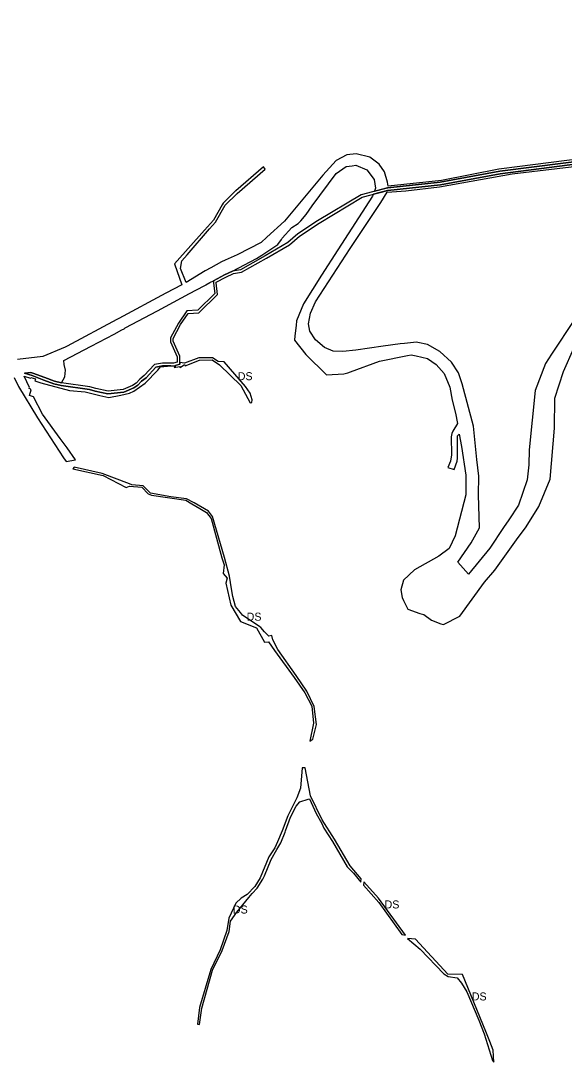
# Model space of a CAD drawing. Extents: x -477304 to -465641, y -1159113 to -1149285.
# Drawn here: x -467453 to -466842, y -1153824 to -1152653 of the extents above; entities that cross this region are included whole.
import ezdxf

# ---------------------------------------------------------------- set-up
doc = ezdxf.new("R2010")
doc.units = 0
doc.layers.add('14', color=7, linetype='Continuous')
doc.layers.add('35', color=7, linetype='Continuous')

msp = doc.modelspace()

# ---------------------------------------------------------------- linework, layer by layer
at = {"layer": '14'}
for p, q in [((-467205.9, -1152933), (-467214.8, -1152934.5)), ((-467213.9, -1152937.4), (-467204.9, -1152935.9)), ((-467441.8, -1153048.4), (-467448.7, -1153049.2))]:
    msp.add_line(p, q, dxfattribs=at)
for points in [[(-466804.8, -1152808.2), (-466914.5, -1152822.2), (-466981.4, -1152834.6), (-467040.8, -1152840.9), (-467070.4, -1152848.7), (-467119.3, -1152878), (-467141.7, -1152892.8), (-467152.7, -1152902.5), (-467178.1, -1152917.5), (-467205.9, -1152933)], [(-467204.9, -1152935.9), (-467176.6, -1152920.1), (-467151, -1152905), (-467139.8, -1152895.2), (-467117.7, -1152880.6), (-467069.2, -1152851.5), (-467040.2, -1152843.9), (-466981, -1152837.6), (-466914, -1152825.2), (-466803.9, -1152811.1)], [(-467448.7, -1153049.2), (-467440.3, -1153052.1), (-467427, -1153057.1), (-467415.7, -1153061.3), (-467407.7, -1153063.1), (-467375.9, -1153067.8), (-467369.4, -1153069.6), (-467355, -1153072.4), (-467337.1, -1153070.7), (-467325.9, -1153065.8), (-467321.5, -1153062.7), (-467317.3, -1153058.3), (-467312.2, -1153054.4), (-467301, -1153042.4), (-467293.6, -1153041), (-467280.8, -1153041.1), (-467274, -1153039.3), (-467274.1, -1153030.3), (-467281.6, -1153013.3), (-467281.7, -1153010.2), (-467273.3, -1152994.6), (-467264.7, -1152982.1), (-467252.7, -1152981.4), (-467231.8, -1152960.9), (-467233.2, -1152947.7), (-467233.3, -1152947.1), (-467222.6, -1152941.3), (-467213.9, -1152937.4)], [(-467214.8, -1152934.5), (-467223.9, -1152938.6), (-467236.5, -1152945.4), (-467236.2, -1152948), (-467235, -1152959.8), (-467254, -1152978.4), (-467266.3, -1152979.2), (-467275.8, -1152993.1), (-467284.7, -1153009.4), (-467284.5, -1153013.9), (-467277.1, -1153030.9), (-467277, -1153037), (-467281.2, -1153038.1), (-467293.8, -1153038), (-467302.5, -1153039.6), (-467314.2, -1153052.1), (-467319.3, -1153056.1), (-467323.4, -1153060.4), (-467327.4, -1153063.1), (-467337.9, -1153067.8), (-467354.8, -1153069.4), (-467368.7, -1153066.6), (-467375.3, -1153064.8), (-467407.2, -1153060.1), (-467414.9, -1153058.4), (-467426, -1153054.3), (-467439.3, -1153049.3), (-467441.8, -1153048.4)]]:
    msp.add_lwpolyline(points, dxfattribs=at)
at = {"layer": '35'}
for p, q in [((-467075.9, -1152802.6), (-467086.5, -1152803.7)), ((-467060.5, -1152806.4), (-467075.9, -1152802.6)), ((-467050, -1152814.3), (-467060.5, -1152806.4)), ((-467209.7, -1152847.2), (-467178.2, -1152820.1)), ((-467178.2, -1152820.1), (-467180.1, -1152817.5)), ((-467080.5, -1152816.2), (-467076.3, -1152815.6)), ((-467044.1, -1152822.8), (-467050, -1152814.3)), ((-466915.7, -1152820.1), (-466980, -1152832.7)), ((-466891.8, -1152816.9), (-466915.7, -1152820.1)), ((-466980, -1152832.7), (-467040, -1152839.1)), ((-467223.2, -1152860.3), (-467209.7, -1152847.2)), ((-467211.8, -1152844.8), (-467221.5, -1152854.2)), ((-467056.6, -1152848.2), (-467057.5, -1152850.5)), ((-467040.7, -1152844), (-467056.6, -1152848.2)), ((-467041, -1152845.7), (-467020, -1152844.3)), ((-467226.7, -1152860.1), (-467236.4, -1152877.2)), ((-467234.2, -1152879.5), (-467223.2, -1152860.3)), ((-467057.5, -1152850.5), (-467096.6, -1152910.6)), ((-467138.3, -1152878), (-467132, -1152870.8)), ((-467132, -1152870.8), (-467125.6, -1152861.2)), ((-467236.4, -1152877.2), (-467246.5, -1152888.6)), ((-467156.6, -1152878.6), (-467176.2, -1152896.6)), ((-467246.5, -1152888.6), (-467280, -1152926.4)), ((-467181.9, -1152916.8), (-467163.9, -1152904.7)), ((-467163.9, -1152904.7), (-467160, -1152898.9)), ((-467160, -1152898.9), (-467159, -1152897.7)), ((-467209.8, -1152916.1), (-467219.9, -1152920.7)), ((-467280, -1152926.4), (-467272.1, -1152950)), ((-467239.5, -1152930.8), (-467245.7, -1152934.3)), ((-467227.4, -1152924), (-467239.5, -1152930.8)), ((-467267, -1152947.3), (-467273.5, -1152931.5)), ((-467245.7, -1152934.3), (-467267, -1152947.3)), ((-467236.5, -1152945.4), (-467223.9, -1152938.6)), ((-467223.9, -1152938.6), (-467214.8, -1152934.5)), ((-467272.1, -1152950), (-467290.1, -1152959.5)), ((-467263.2, -1152959.8), (-467246.8, -1152951)), ((-467246.8, -1152951), (-467245.5, -1152950.3)), ((-467240.3, -1152947.5), (-467236.5, -1152945.4)), ((-467290.1, -1152959.5), (-467342.9, -1152987.8)), ((-467345, -1152988.9), (-467401, -1153018.9)), ((-467342.9, -1152987.8), (-467345, -1152988.9)), ((-467129.6, -1152993.9), (-467127.4, -1152981.7)), ((-467348, -1153005.3), (-467339.4, -1153000.7)), ((-467339.4, -1153000.7), (-467336.8, -1152999.4)), ((-467336.8, -1152999.4), (-467335.8, -1152998.5)), ((-467128, -1153002.1), (-467129.6, -1152993.9)), ((-467373.8, -1153019), (-467348, -1153005.3)), ((-467145, -1153007.2), (-467145.3, -1153012.2)), ((-467145.3, -1153012.2), (-467132.5, -1153028.2)), ((-467121.8, -1153011.9), (-467128, -1153002.1)), ((-467403.2, -1153020.1), (-467428.2, -1153030.5)), ((-467404.5, -1153035.1), (-467373.8, -1153019)), ((-467401, -1153018.9), (-467403.2, -1153020.1)), ((-467008.2, -1153014.5), (-467021.6, -1153015.9)), ((-467006.6, -1153014.8), (-467008.2, -1153014.5)), ((-467428.2, -1153030.5), (-467456.6, -1153033.8)), ((-467404.2, -1153039.6), (-467404.5, -1153035.1)), ((-467252.8, -1153032.1), (-467269, -1153038.1)), ((-467268.1, -1153040.9), (-467252, -1153034.7)), ((-467237.5, -1153031.9), (-467252.8, -1153032.1)), ((-467231.1, -1153036), (-467237.5, -1153031.9)), ((-467224.3, -1153036.5), (-467231.1, -1153036)), ((-467132.5, -1153028.2), (-467109.2, -1153051.2)), ((-467049.9, -1153035.7), (-467018.1, -1153029.4)), ((-467018.1, -1153029.4), (-467014.2, -1153028.6)), ((-467014.2, -1153028.6), (-467008.6, -1153029.9)), ((-467008.6, -1153029.9), (-466995.8, -1153032.7)), ((-467313.2, -1153060.5), (-467298.9, -1153045.9)), ((-467298.9, -1153045.9), (-467295.9, -1153042.2)), ((-467295.9, -1153042.2), (-467284.2, -1153041.1)), ((-467284.2, -1153041.1), (-467293.6, -1153041)), ((-467279.1, -1153040.6), (-467280.4, -1153043)), ((-467280.4, -1153043), (-467274.4, -1153041.7)), ((-467274, -1153039.3), (-467279.1, -1153040.6)), ((-467274.4, -1153041.7), (-467273.7, -1153042.8)), ((-467269, -1153038.1), (-467274, -1153037.4)), ((-467274, -1153037.4), (-467274, -1153039.3)), ((-467443, -1153065.3), (-467449.2, -1153052.5)), ((-467449.2, -1153052.5), (-467442, -1153055)), ((-467448.7, -1153049.2), (-467441.8, -1153048.4)), ((-467442, -1153055), (-467441.6, -1153054)), ((-467441.8, -1153048.4), (-467439.3, -1153049.3)), ((-467441.6, -1153054), (-467436.6, -1153055.6)), ((-467436.6, -1153055.6), (-467437.3, -1153057.8)), ((-467437.3, -1153057.8), (-467430.4, -1153060.1)), ((-467407.2, -1153060.1), (-467403.3, -1153053.4)), ((-467109.2, -1153051.2), (-467090, -1153050)), ((-466977.1, -1153049.5), (-466970.5, -1153065)), ((-466956.9, -1153061.2), (-466961.1, -1153048.9)), ((-467443.3, -1153074.4), (-467441.2, -1153068.1)), ((-467441.8, -1153067.9), (-467441.6, -1153067.4)), ((-467441.2, -1153068.1), (-467441.8, -1153067.9)), ((-467380.6, -1153070.3), (-467364, -1153074.4)), ((-467330.6, -1153071.9), (-467325.9, -1153069.4)), ((-467325.9, -1153069.4), (-467313.2, -1153060.5)), ((-467205.6, -1153063.2), (-467195, -1153082.5)), ((-466970.5, -1153065), (-466968.2, -1153079.5)), ((-467438.7, -1153075.9), (-467443.3, -1153074.4)), ((-467340.4, -1153074.2), (-467330.6, -1153071.9)), ((-467195, -1153082.5), (-467193.4, -1153082.1)), ((-467193.4, -1153082.1), (-467193, -1153079.2)), ((-466968.2, -1153079.5), (-466964.2, -1153094.2)), ((-466964.2, -1153094.2), (-466962.1, -1153106)), ((-466962.1, -1153106), (-466967.4, -1153114.5)), ((-466968.5, -1153117.2), (-466969.2, -1153120.7)), ((-466967.4, -1153114.5), (-466968.5, -1153117.2)), ((-466960.1, -1153117.7), (-466957.6, -1153131.8)), ((-467400.7, -1153133.4), (-467408.7, -1153122.7)), ((-466969.2, -1153120.7), (-466968.9, -1153141.2)), ((-467391.6, -1153146.8), (-467400.7, -1153133.4)), ((-466968.9, -1153141.2), (-466970, -1153148.2)), ((-466957.6, -1153131.8), (-466952.6, -1153163.9)), ((-467402.1, -1153148.5), (-467391.6, -1153146.8)), ((-466970, -1153148.2), (-466972.8, -1153155.3)), ((-466938.1, -1153165.1), (-466940.4, -1153146.2)), ((-466881.9, -1153152.3), (-466883.8, -1153169.2)), ((-467393.1, -1153154.9), (-467394.5, -1153157)), ((-467394.5, -1153157), (-467360.3, -1153164.2)), ((-467361.3, -1153162.1), (-467393.1, -1153154.9)), ((-467330.9, -1153173.7), (-467361.3, -1153162.1)), ((-467360.3, -1153164.2), (-467334.5, -1153178)), ((-466972.8, -1153155.3), (-466965.9, -1153157.7)), ((-466952.6, -1153163.9), (-466952.8, -1153185.9)), ((-466938.4, -1153186.1), (-466938.1, -1153165.1)), ((-467334.5, -1153178), (-467330.6, -1153176.5)), ((-467328.2, -1153174.8), (-467330.9, -1153173.7)), ((-467315.3, -1153175.9), (-467328.2, -1153174.8)), ((-467307.3, -1153184.2), (-467315.3, -1153175.9)), ((-466883.8, -1153169.2), (-466893.6, -1153197.5)), ((-467309.8, -1153184.9), (-467306.2, -1153186.6)), ((-467284.2, -1153188.3), (-467307.3, -1153184.2)), ((-466952.8, -1153185.9), (-466964.6, -1153232.3)), ((-466937.3, -1153223.3), (-466938.4, -1153186.1)), ((-467260.6, -1153196.2), (-467251.7, -1153201.3)), ((-467242.1, -1153204.5), (-467258.2, -1153195.1)), ((-466884.9, -1153221.9), (-466870.5, -1153199.2)), ((-467251.7, -1153201.3), (-467244.1, -1153205.8)), ((-467244.1, -1153205.8), (-467238.8, -1153212.7)), ((-467237.4, -1153210.6), (-467242.1, -1153204.5)), ((-467224.1, -1153256.6), (-467237.4, -1153210.6)), ((-467238.8, -1153212.7), (-467227.1, -1153256.7)), ((-466946.6, -1153240.1), (-466937.3, -1153223.3)), ((-466910.3, -1153222.9), (-466925.7, -1153246)), ((-466895.7, -1153236.5), (-466884.9, -1153221.9)), ((-466964.6, -1153232.3), (-466971.3, -1153246.2)), ((-466971.3, -1153246.2), (-466983.1, -1153255.1)), ((-466961.8, -1153261.9), (-466946.6, -1153240.1)), ((-466925.7, -1153246), (-466949.6, -1153275.4)), ((-466920.2, -1153270.8), (-466895.7, -1153236.5)), ((-467218.5, -1153277.3), (-467224.1, -1153256.6)), ((-466983.1, -1153255.1), (-467010.5, -1153270.2)), ((-467010.5, -1153270.2), (-467022.6, -1153281.8)), ((-466949.6, -1153275.4), (-466961.8, -1153261.9)), ((-467225.4, -1153274.6), (-467221.1, -1153279.7)), ((-467216.1, -1153291.9), (-467218.5, -1153277.3)), ((-467022.6, -1153281.8), (-467025.7, -1153293)), ((-466931.8, -1153284.4), (-466920.2, -1153270.8)), ((-467214.7, -1153300.2), (-467216.1, -1153291.9)), ((-467025.7, -1153293), (-467024.4, -1153301.5)), ((-466959.5, -1153322.4), (-466931.8, -1153284.4)), ((-467211.6, -1153311.4), (-467214.7, -1153300.2)), ((-467024.4, -1153301.5), (-467022.8, -1153304.7)), ((-467022.8, -1153304.7), (-467017.8, -1153314.4)), ((-467216.8, -1153310.1), (-467206.1, -1153328.4)), ((-467205.8, -1153318.5), (-467211.6, -1153311.4)), ((-467017.8, -1153314.4), (-467004.4, -1153319.6)), ((-467206.1, -1153328.4), (-467187.9, -1153335.7)), ((-467004.4, -1153319.6), (-467000, -1153320.4)), ((-467000, -1153320.4), (-466991.1, -1153327.1)), ((-466991.1, -1153327.1), (-466980.8, -1153330.9)), ((-466977.8, -1153331.9), (-466959.5, -1153322.4)), ((-467187.9, -1153335.7), (-467179.1, -1153351.7)), ((-467183.3, -1153335.3), (-467184.2, -1153334.3)), ((-467178.9, -1153340.1), (-467183.3, -1153335.3)), ((-466980.8, -1153330.9), (-466977.8, -1153331.9)), ((-467143.3, -1153389), (-467163.9, -1153360)), ((-467145.8, -1153391.3), (-467133.5, -1153408.6)), ((-467131.4, -1153406.7), (-467143.3, -1153389)), ((-467133.5, -1153408.6), (-467125.7, -1153423.8)), ((-467123.2, -1153423.9), (-467131.4, -1153406.7)), ((-467125.7, -1153423.8), (-467123.8, -1153442.8)), ((-467120.7, -1153444.2), (-467123.2, -1153423.9)), ((-467123.8, -1153442.8), (-467128.1, -1153462.8)), ((-467124.6, -1153460.7), (-467120.7, -1153444.2)), ((-467128.1, -1153462.8), (-467124.6, -1153460.7)), ((-467133.4, -1153493.1), (-467136.5, -1153492.8)), ((-467127.4, -1153524.5), (-467133.4, -1153493.1)), ((-467142.5, -1153526.7), (-467152.9, -1153546.9)), ((-467129.9, -1153528.1), (-467128.5, -1153527.7)), ((-467128.5, -1153527.7), (-467120.8, -1153544.3)), ((-467114.1, -1153551.4), (-467127.4, -1153524.5)), ((-467139.3, -1153531.1), (-467129.9, -1153528.1)), ((-467152.9, -1153546.9), (-467159.3, -1153563.9)), ((-467155.3, -1153563.7), (-467149.6, -1153548.5)), ((-467120.8, -1153544.3), (-467114.7, -1153555.6)), ((-467159.3, -1153563.9), (-467164.4, -1153576.1)), ((-467171.4, -1153595.8), (-467165, -1153584.7)), ((-467165, -1153584.7), (-467160.8, -1153577.4)), ((-467179, -1153614.3), (-467171.4, -1153595.8)), ((-467187.4, -1153628.2), (-467180.8, -1153618.2)), ((-467180.8, -1153618.2), (-467179, -1153614.3)), ((-467079.1, -1153611.2), (-467070.6, -1153621.4)), ((-467070.6, -1153621.4), (-467070.2, -1153617.8)), ((-467192.7, -1153634.3), (-467187.4, -1153628.2)), ((-467205.2, -1153639.5), (-467211.4, -1153645.2)), ((-467020.5, -1153680.9), (-467050.8, -1153639.4)), ((-467217.3, -1153665.2), (-467210.2, -1153655.1)), ((-467221.2, -1153675.7), (-467228.9, -1153697.4)), ((-467024.5, -1153680.4), (-467020.5, -1153680.9)), ((-467009.2, -1153685.7), (-467018.3, -1153684.9)), ((-467018.3, -1153684.9), (-467004.1, -1153696.9)), ((-466972.9, -1153724.8), (-467009.2, -1153685.7)), ((-467004.1, -1153696.9), (-466977.5, -1153724.6)), ((-466977.5, -1153724.6), (-466972.5, -1153727.3)), ((-466972.5, -1153727.3), (-466962.5, -1153728.9)), ((-466962.5, -1153728.9), (-466957.5, -1153735.1)), ((-467252, -1153781.4), (-467249.5, -1153763.2)), ((-466938.1, -1153776.5), (-466932, -1153792)), ((-466932, -1153792), (-466922.8, -1153821.8)), ((-466921.9, -1153810.4), (-466925.8, -1153800.4)), ((-466921.2, -1153823.8), (-466921.9, -1153810.4)), ((-466922.8, -1153821.8), (-466921.2, -1153823.8))]:
    msp.add_line(p, q, dxfattribs=at)
for points in [[(-465976, -1152655.9), (-465999.4, -1152663.2), (-466077.9, -1152694.1), (-466164.6, -1152739.6), (-466225.4, -1152735), (-466242.9, -1152734.6), (-466260.3, -1152738.5), (-466326.5, -1152756), (-466358.9, -1152753), (-466453.6, -1152743.5), (-466463.9, -1152741.4), (-466475.6, -1152737.8), (-466495.4, -1152718.1), (-466506.6, -1152710.6), (-466525.4, -1152705.5), (-466529.6, -1152706.1), (-466710.9, -1152767.2), (-466803.9, -1152811.1), (-466914, -1152825.2), (-466981, -1152837.6), (-467040.2, -1152843.9), (-467040.7, -1152844)], [(-467040.2, -1152840.8), (-466981.4, -1152834.6), (-466914.5, -1152822.2), (-466804.8, -1152808.2), (-466712.1, -1152764.4), (-466530.3, -1152703.2), (-466525.3, -1152702.4), (-466505.4, -1152707.9), (-466493.5, -1152715.7), (-466474, -1152735.2), (-466463.2, -1152738.4), (-466453.2, -1152740.5), (-466358.7, -1152750), (-466326.7, -1152752.9), (-466261, -1152735.6), (-466243.2, -1152731.6), (-466225.2, -1152732), (-466165.2, -1152736.6), (-466079.1, -1152691.4), (-466000.4, -1152660.4), (-465977.5, -1152653.2)], [(-466714, -1152762.3), (-466777.8, -1152791.4), (-466806.9, -1152806.1), (-466891.8, -1152816.9)], [(-467086.5, -1152803.7), (-467098.4, -1152810.2), (-467113.3, -1152826.6), (-467156.6, -1152878.6)], [(-467180.1, -1152817.5), (-467211.4, -1152844.4), (-467211.8, -1152844.8)], [(-467125.6, -1152861.2), (-467098.4, -1152824.7), (-467087.2, -1152817.1), (-467080.5, -1152816.2)], [(-467076.3, -1152815.6), (-467063.9, -1152820.9), (-467055.8, -1152831.5), (-467054.2, -1152841.4), (-467055.4, -1152844.7)], [(-467040, -1152839.1), (-467040.7, -1152834.5), (-467044.1, -1152822.8)], [(-467020, -1152844.3), (-466982.1, -1152839.9), (-466900.7, -1152825.3), (-466828, -1152816.6)], [(-467127.4, -1152981.7), (-467121.5, -1152969.2), (-467082.7, -1152909), (-467048.2, -1152857.6), (-467041, -1152845.7)], [(-467055.4, -1152844.7), (-467040.8, -1152840.9), (-467040.2, -1152840.8)], [(-467221.5, -1152854.2), (-467225.6, -1152858.2), (-467226.7, -1152860.1)], [(-467273.5, -1152931.5), (-467272.1, -1152923.1), (-467266.1, -1152916.1), (-467240.7, -1152887), (-467234.2, -1152879.5)], [(-467159, -1152897.7), (-467148.1, -1152885.5), (-467141, -1152881), (-467138.3, -1152878)], [(-467176.2, -1152896.6), (-467182.8, -1152902.6), (-467209.8, -1152916.1)], [(-467214.8, -1152934.5), (-467188.1, -1152920.3), (-467181.9, -1152916.8)], [(-467096.6, -1152910.6), (-467115, -1152939), (-467135.3, -1152971.3), (-467142.9, -1152990.4), (-467143.5, -1152995.6), (-467145, -1153007.2)], [(-467219.9, -1152920.7), (-467223.2, -1152922.2), (-467227.4, -1152924)], [(-467245.5, -1152950.3), (-467244.8, -1152949.9), (-467240.3, -1152947.5)], [(-467335.8, -1152998.5), (-467299.3, -1152979.3), (-467263.2, -1152959.8)], [(-466783.3, -1152962.3), (-466798.8, -1152967.1), (-466809.2, -1152971.3), (-466830.7, -1152988.9), (-466856.5, -1153028), (-466863.1, -1153038.4), (-466874.7, -1153068.8)], [(-467076.3, -1153023.5), (-467091.1, -1153025), (-467101.9, -1153024.6), (-467111.5, -1153020.3), (-467121.8, -1153011.9)], [(-467021.6, -1153015.9), (-467026.5, -1153016.4), (-467045.5, -1153019.1), (-467076.3, -1153023.5)], [(-466981.8, -1153024.9), (-466995.7, -1153017.1), (-467006.6, -1153014.8)], [(-466853.1, -1153111), (-466852.6, -1153077.3), (-466843, -1153047.3), (-466831.1, -1153021.2)], [(-467252, -1153034.7), (-467238, -1153034.3), (-467229.6, -1153040), (-467205.6, -1153063.2)], [(-467090, -1153050), (-467085.5, -1153049), (-467082.3, -1153047.8), (-467049.9, -1153035.7)], [(-466995.8, -1153032.7), (-466985.9, -1153039.6), (-466977.1, -1153049.5)], [(-466961.1, -1153048.9), (-466968.7, -1153036.8), (-466981.8, -1153024.9)], [(-467293.6, -1153041), (-467301, -1153042.4), (-467312.2, -1153054.4), (-467317.3, -1153058.3), (-467321.5, -1153062.7), (-467325.9, -1153065.8), (-467337.1, -1153070.7), (-467355, -1153072.4), (-467369.4, -1153069.6), (-467375.9, -1153067.8), (-467407.7, -1153063.1), (-467415.7, -1153061.3), (-467427, -1153057.1), (-467440.3, -1153052.1), (-467448.7, -1153049.2)], [(-467403.3, -1153053.4), (-467402.8, -1153046.1), (-467404.2, -1153039.6)], [(-467273.7, -1153042.8), (-467268.9, -1153039.7), (-467268.1, -1153040.9)], [(-467193, -1153079.2), (-467195.3, -1153071.8), (-467200.3, -1153064.2), (-467224.3, -1153036.5)], [(-467460.5, -1153054), (-467455.4, -1153064.2), (-467434.1, -1153099.4), (-467404.8, -1153144.4), (-467402.1, -1153148.5)], [(-467439.3, -1153049.3), (-467426, -1153054.3), (-467414.9, -1153058.4), (-467407.2, -1153060.1)], [(-467441.6, -1153067.4), (-467443.5, -1153066.7), (-467443, -1153065.3)], [(-467430.4, -1153060.1), (-467398.2, -1153068.6), (-467380.6, -1153070.3)], [(-466940.4, -1153146.2), (-466944.2, -1153109), (-466956.9, -1153061.2)], [(-466874.7, -1153068.8), (-466881.5, -1153135.3), (-466881.9, -1153152.3)], [(-467408.7, -1153122.7), (-467428.6, -1153095.4), (-467438.7, -1153075.9)], [(-467364, -1153074.4), (-467353.9, -1153076.8), (-467340.4, -1153074.2)], [(-466961.9, -1153144.7), (-466962.1, -1153119.9), (-466960.1, -1153117.7)], [(-466870.5, -1153199.2), (-466857.7, -1153168.4), (-466853.1, -1153111)], [(-466965.9, -1153157.7), (-466962.5, -1153148.3), (-466961.9, -1153144.7)], [(-467330.6, -1153176.5), (-467316.9, -1153177.3), (-467309.8, -1153184.9)], [(-467306.2, -1153186.6), (-467267.6, -1153192.1), (-467260.6, -1153196.2)], [(-467258.2, -1153195.1), (-467266.7, -1153190.7), (-467284.2, -1153188.3)], [(-466893.6, -1153197.5), (-466904.4, -1153214), (-466910.3, -1153222.9)], [(-467227.1, -1153256.7), (-467224.2, -1153264.9), (-467225.4, -1153274.6)], [(-467221.1, -1153279.7), (-467222.4, -1153285.5), (-467216.8, -1153310.1)], [(-467184.2, -1153334.3), (-467203.8, -1153321.2), (-467205.8, -1153318.5)], [(-467170.7, -1153344.3), (-467174.2, -1153345), (-467178.9, -1153340.1)], [(-467179.1, -1153351.7), (-467174.4, -1153351.3), (-467167.6, -1153361), (-467145.8, -1153391.3)], [(-467163.9, -1153360), (-467169.6, -1153349.2), (-467170.7, -1153344.3)], [(-467136.5, -1153492.8), (-467138.6, -1153515.6), (-467142.5, -1153526.7)], [(-467149.6, -1153548.5), (-467143.5, -1153535.9), (-467139.3, -1153531.1)], [(-467070.2, -1153617.8), (-467082.7, -1153603), (-467100.5, -1153573), (-467114.1, -1153551.4)], [(-467114.7, -1153555.6), (-467112.2, -1153560.8), (-467102.4, -1153575.8)], [(-467160.8, -1153577.4), (-467155.9, -1153565.1), (-467155.3, -1153563.7)], [(-467164.4, -1153576.1), (-467167.4, -1153582.7), (-467174, -1153593.1), (-467183.8, -1153616.7), (-467189.8, -1153626.2), (-467198.6, -1153635.4), (-467205.2, -1153639.5)], [(-467102.4, -1153575.8), (-467086.1, -1153604.1), (-467079.1, -1153611.2)], [(-467050.8, -1153639.4), (-467067.4, -1153621), (-467067.7, -1153624.7), (-467050.5, -1153644.4), (-467024.5, -1153680.4)], [(-467210.2, -1153655.1), (-467196.6, -1153638.6), (-467192.7, -1153634.3)], [(-467211.4, -1153645.2), (-467219.2, -1153662.1), (-467221.2, -1153675.7)], [(-467226.5, -1153698.1), (-467218.9, -1153676.9), (-467217.3, -1153665.2)], [(-467228.9, -1153697.4), (-467239.2, -1153719.7), (-467251.9, -1153762.4), (-467254.4, -1153781.1), (-467252, -1153781.4)], [(-467249.5, -1153763.2), (-467237.4, -1153720.3), (-467226.5, -1153698.1)], [(-466925.8, -1153800.4), (-466930.2, -1153789.2), (-466956.5, -1153725.4), (-466972.9, -1153724.8)], [(-466957.5, -1153735.1), (-466951.6, -1153744.7), (-466938.1, -1153776.5)]]:
    msp.add_lwpolyline(points, dxfattribs=at)

# ---------------------------------------------------------------- texts
for p in [(-467209.1, -1153057.2), (-467199.1, -1153327.5), (-467044.1, -1153651), (-467214.6, -1153656.7), (-466946, -1153754.4)]:
    msp.add_text('DS', height=9, dxfattribs=at).set_placement(p)

doc.saveas('drawing.dxf')
